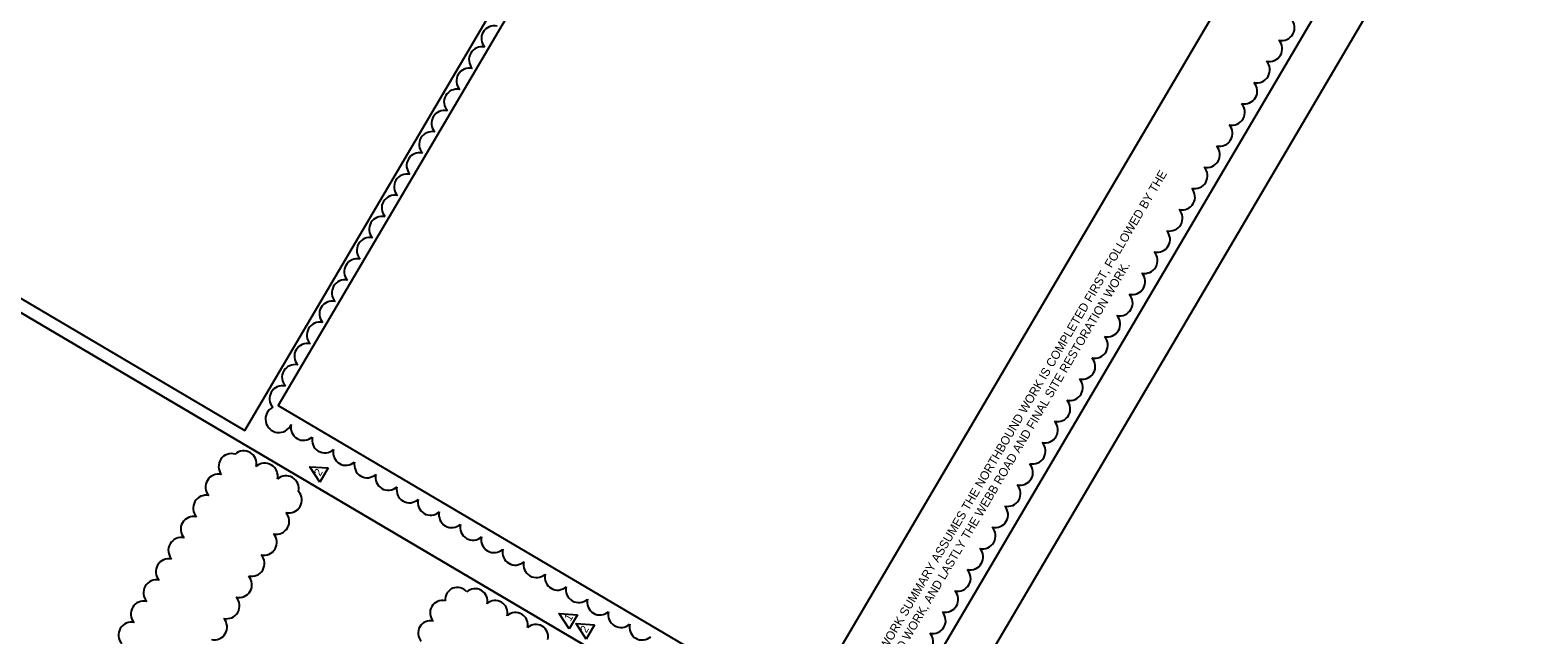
# Model space of a CAD drawing. Extents: x 12 to 1151523, y -64 to 610812.
# Drawn here: x 1151171.669 to 1151173.408, y 610616.617 to 610617.314 of the extents above; entities that cross this region are included whole.
import ezdxf

# ---------------------------------------------------------------- set-up
doc = ezdxf.new("R2010")
doc.units = 0
for name, color, linetype in [('ANNOTATION', 7, 'Continuous'), ('BANNOTATION', 7, 'Continuous'), ('BORDER', 7, 'Continuous'), ('DIMENSIONS', 7, 'Continuous'), ('PLOT BOUNDARY', 7, 'Continuous')]:
    doc.layers.add(name, color=color, linetype=linetype)

msp = doc.modelspace()

# ---------------------------------------------------------------- linework, layer by layer
at = {"layer": 'ANNOTATION'}
for points in [[(1151171.9166, 610616.8528), (1151172.5327, 610617.8987), (1151171.737, 610618.3673), (1151171.121, 610617.3214)], [(1151171.9166, 610616.8528), (1151172.5327, 610617.8987), (1151171.737, 610618.3673), (1151171.121, 610617.3214)], [(1151172.5585, 610616.5257), (1151173.1433, 610617.5186), (1151172.5397, 610617.8742), (1151171.9549, 610616.8813)], [(1151170.4975, 610616.263), (1151171.1137, 610617.309), (1151172.6047, 610616.4307), (1151171.9886, 610615.3847)], [(1151171.9886, 610615.3847), (1151172.6047, 610616.4307), (1151171.1137, 610617.309), (1151170.4975, 610616.263)]]:
    msp.add_lwpolyline(points, close=True, dxfattribs=at)
for centre, radius, start, end in [((1151173.1124, 610617.3168), 0.0148, 257.0011, 42.0011), ((1151172.2041, 610617.3041), 0.0148, 77.0011, 222.0011), ((1151172.1898, 610617.2797), 0.0148, 77.0011, 222.0011), ((1151173.0981, 610617.2924), 0.0148, 257.0011, 42.0011), ((1151173.0837, 610617.268), 0.0148, 257.0011, 42.0011), ((1151172.1754, 610617.2553), 0.0148, 77.0011, 222.0011), ((1151172.161, 610617.2309), 0.0148, 77.0011, 222.0011), ((1151173.0693, 610617.2436), 0.0148, 257.0011, 42.0011), ((1151172.1466, 610617.2065), 0.0148, 77.0011, 222.0011), ((1151173.055, 610617.2192), 0.0148, 257.0011, 42.0011), ((1151173.0406, 610617.1948), 0.0148, 257.0011, 42.0011), ((1151172.1323, 610617.1821), 0.0148, 77.0011, 222.0011), ((1151172.1179, 610617.1577), 0.0148, 77.0011, 222.0011), ((1151173.0262, 610617.1704), 0.0148, 257.0011, 42.0011), ((1151173.0118, 610617.146), 0.0148, 257.0011, 42.0011), ((1151172.1035, 610617.1333), 0.0148, 77.0011, 222.0011), ((1151172.0892, 610617.1089), 0.0148, 77.0011, 222.0011), ((1151172.9975, 610617.1216), 0.0148, 257.0011, 42.0011), ((1151172.9831, 610617.0972), 0.0148, 257.0011, 42.0011), ((1151172.0748, 610617.0845), 0.0148, 77.0011, 222.0011), ((1151172.9687, 610617.0728), 0.0148, 257.0011, 42.0011), ((1151172.0604, 610617.0601), 0.0148, 77.0011, 222.0011), ((1151172.046, 610617.0357), 0.0148, 77.0011, 222.0011), ((1151172.9543, 610617.0484), 0.0148, 257.0011, 42.0011), ((1151172.94, 610617.024), 0.0148, 257.0011, 42.0011), ((1151172.0317, 610617.0113), 0.0148, 77.0011, 222.0011), ((1151172.0173, 610616.9869), 0.0148, 77.0011, 222.0011), ((1151172.9256, 610616.9996), 0.0148, 257.0011, 42.0011), ((1151172.9112, 610616.9752), 0.0148, 257.0011, 42.0011), ((1151172.0029, 610616.9625), 0.0148, 77.0011, 222.0011), ((1151172.8969, 610616.9508), 0.0148, 257.0011, 42.0011), ((1151171.9885, 610616.9381), 0.0148, 77.0011, 222.0011), ((1151171.9742, 610616.9137), 0.0148, 77.0011, 222.0011), ((1151172.8825, 610616.9264), 0.0148, 257.0011, 42.0011), ((1151172.8681, 610616.902), 0.0148, 257.0011, 42.0011), ((1151171.9598, 610616.8893), 0.0148, 77.0011, 222.0011), ((1151171.9558, 610616.8656), 0.0154, 117.0307, 336.2971), ((1151171.9558, 610616.8656), 0.0154, 117.0307, 336.2971), ((1151172.8537, 610616.8776), 0.0148, 257.0011, 42.0011), ((1151171.9844, 610616.8561), 0.0148, 167.0011, 312.0011), ((1151171.9844, 610616.8561), 0.0148, 167.0011, 312.0011), ((1151172.8394, 610616.8532), 0.0148, 257.0011, 42.0011), ((1151172.0088, 610616.8417), 0.0148, 167.0011, 312.0011), ((1151172.0088, 610616.8417), 0.0148, 167.0011, 312.0011), ((1151172.825, 610616.8288), 0.0148, 257.0011, 42.0011), ((1151171.9011, 610616.8112), 0.0148, 73.3175, 218.3175), ((1151171.9153, 610616.8144), 0.0148, 347.0011, 132.0011), ((1151172.0332, 610616.8273), 0.0148, 167.0011, 312.0011), ((1151172.0332, 610616.8273), 0.0148, 167.0011, 312.0011), ((1151171.9397, 610616.8001), 0.0148, 347.0011, 132.0011), ((1151172.0576, 610616.813), 0.0148, 167.0011, 312.0011), ((1151172.0576, 610616.813), 0.0148, 167.0011, 312.0011), ((1151172.8106, 610616.8044), 0.0148, 257.0011, 42.0011), ((1151171.8861, 610616.7876), 0.0148, 77.0011, 222.0011), ((1151171.964, 610616.7857), 0.0148, 347.0011, 132.0011), ((1151172.082, 610616.7986), 0.0148, 167.0011, 312.0011), ((1151172.082, 610616.7986), 0.0148, 167.0011, 312.0011), ((1151172.1064, 610616.7842), 0.0148, 167.0011, 312.0011), ((1151172.1064, 610616.7842), 0.0148, 167.0011, 312.0011), ((1151172.7963, 610616.78), 0.0148, 257.0011, 42.0011), ((1151171.8718, 610616.7632), 0.0148, 77.0011, 222.0011), ((1151171.9675, 610616.7725), 0.0148, 257.0011, 42.0011), ((1151172.1308, 610616.7698), 0.0148, 167.0011, 312.0011), ((1151172.1308, 610616.7698), 0.0148, 167.0011, 312.0011), ((1151171.8574, 610616.7388), 0.0148, 77.0011, 222.0011), ((1151171.9531, 610616.7481), 0.0148, 257.0011, 42.0011), ((1151172.1552, 610616.7555), 0.0148, 167.0011, 312.0011), ((1151172.1552, 610616.7555), 0.0148, 167.0011, 312.0011), ((1151172.7819, 610616.7556), 0.0148, 257.0011, 42.0011), ((1151172.1796, 610616.7411), 0.0148, 167.0011, 312.0011), ((1151172.1796, 610616.7411), 0.0148, 167.0011, 312.0011), ((1151172.7675, 610616.7312), 0.0148, 257.0011, 42.0011), ((1151171.8431, 610616.7145), 0.0148, 77.0011, 222.0011), ((1151171.9387, 610616.7237), 0.0148, 257.0011, 42.0011), ((1151172.204, 610616.7267), 0.0148, 167.0011, 312.0011), ((1151172.204, 610616.7267), 0.0148, 167.0011, 312.0011), ((1151171.8287, 610616.6901), 0.0148, 77.0011, 222.0011), ((1151171.9244, 610616.6994), 0.0148, 257.0011, 42.0011), ((1151172.2284, 610616.7124), 0.0148, 167.0011, 312.0011), ((1151172.2284, 610616.7124), 0.0148, 167.0011, 312.0011), ((1151172.2528, 610616.698), 0.0148, 167.0011, 312.0011), ((1151172.2528, 610616.698), 0.0148, 167.0011, 312.0011), ((1151172.7531, 610616.7068), 0.0148, 257.0011, 42.0011), ((1151171.91, 610616.675), 0.0148, 257.0011, 42.0011), ((1151172.2772, 610616.6836), 0.0148, 167.0011, 312.0011), ((1151172.2772, 610616.6836), 0.0148, 167.0011, 312.0011), ((1151172.7388, 610616.6824), 0.0148, 257.0011, 42.0011), ((1151171.8144, 610616.6657), 0.0148, 77.0011, 222.0011), ((1151172.1617, 610616.6577), 0.0142, 39.8256, 184.8256), ((1151172.1821, 610616.6562), 0.0142, 347.0011, 132.0011), ((1151172.3016, 610616.6692), 0.0148, 167.0011, 312.0011), ((1151172.3016, 610616.6692), 0.0148, 167.0011, 312.0011), ((1151172.7244, 610616.658), 0.0148, 257.0011, 42.0011), ((1151171.8, 610616.6414), 0.0148, 77.0011, 222.0011), ((1151171.8957, 610616.6506), 0.0148, 257.0011, 42.0011), ((1151172.1443, 610616.6426), 0.0142, 77.0011, 222.0011), ((1151172.2054, 610616.6425), 0.0142, 347.0011, 132.0011), ((1151172.326, 610616.6549), 0.0148, 167.0011, 312.0011), ((1151172.326, 610616.6549), 0.0148, 167.0011, 312.0011), ((1151171.7857, 610616.617), 0.0148, 77.0011, 222.0011), ((1151171.8813, 610616.6262), 0.0148, 257.0011, 42.0011), ((1151172.1306, 610616.6193), 0.0142, 77.0011, 222.0011), ((1151172.2288, 610616.6287), 0.0142, 347.0011, 132.0011), ((1151172.3504, 610616.6405), 0.0148, 167.0011, 312.0011), ((1151172.3504, 610616.6405), 0.0148, 167.0011, 312.0011), ((1151172.71, 610616.6336), 0.0148, 257.0011, 42.0011), ((1151172.2522, 610616.615), 0.0142, 347.0011, 132.0011), ((1151172.3748, 610616.6261), 0.0148, 167.0011, 312.0011), ((1151172.3748, 610616.6261), 0.0148, 167.0011, 312.0011), ((1151172.6957, 610616.6092), 0.0148, 257.0011, 42.0011)]:
    msp.add_arc(centre, radius, start, end, dxfattribs=at)
at = {"layer": 'BORDER'}
msp.add_line((1151171.9941, 610615.3677), (1151173.3475, 610617.6654), dxfattribs=at)
at = {"layer": 'DIMENSIONS'}
for p, q in [((1151172.0128, 610616.8095), (1151172.0032, 610616.7932)), ((1151172.3002, 610616.6403), (1151172.2906, 610616.624)), ((1151172.3197, 610616.6287), (1151172.3101, 610616.6124))]:
    msp.add_line(p, q, dxfattribs=at)
for points in [[(1151172.0032, 610616.7932), (1151171.9917, 610616.8109), (1151172.0128, 610616.8095)], [(1151172.2906, 610616.624), (1151172.2792, 610616.6417), (1151172.3002, 610616.6403)], [(1151172.3101, 610616.6124), (1151172.2986, 610616.6302), (1151172.3197, 610616.6287)]]:
    msp.add_lwpolyline(points, dxfattribs=at)
at = {"layer": 'PLOT BOUNDARY'}
msp.add_lwpolyline([(1151171.9696, 610615.2256), (1151173.4076, 610617.6669), (1151171.8279, 610618.5973), (1151170.3899, 610616.156)], close=True, dxfattribs=at)

# ---------------------------------------------------------------- texts
at = {"layer": 'BANNOTATION'}
for s, p in [('THE EARTHWORK SUMMARY ASSUMES THE NORTHBOUND WORK IS COMPLETED FIRST, FOLLOWED BY THE ', (1151172.618, 610616.5334)), ('SOUTHBOUND WORK, AND LASTLY THE WEBB ROAD AND FINAL SITE RESTORATION WORK.', (1151172.6324, 610616.525))]:
    msp.add_text(s, height=0.01, rotation=59.5011, dxfattribs=at).set_placement(p)
at = {"layer": 'DIMENSIONS'}
for s, p in [('2', (1151172.0035, 610616.7994)), ('1', (1151172.2921, 610616.6321)), ('2', (1151172.3104, 610616.6187))]:
    msp.add_text(s, height=0.00907, rotation=59.5011, dxfattribs=at).set_placement(p)

doc.saveas('drawing.dxf')
